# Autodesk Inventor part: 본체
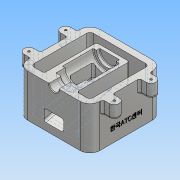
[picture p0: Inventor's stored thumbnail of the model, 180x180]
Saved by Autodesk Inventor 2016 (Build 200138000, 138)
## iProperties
Created: 2018-01
Part Number: 본체
Material: 알루미늄 6061
Document SubType Name: Modeling
Designer: Administrator
Mass: 994.396 g
Surface Area: 835.289 cm^2
Volume: 368.295 cm^3
Density: 2.7 g/cm^3
Appearance: 알루미늄 - 평지
Author: Administrator
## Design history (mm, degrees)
sketch "스케치1"
  geometry: L1 (-55, -55)-(55, -55); L2 (55, -55)-(55, 55); L3 (55, 55)-(-55, 55); L4 (-55, 55)-(-55, -55); L5 (-55, -55)-(55, 55); L6 (55, -55)-(-55, 55); 1 further point
  constraints: 12 end point, 2 midpoint, 2 parallel, 1 horizontal, 1 perpendicular
  dimensions: "d0" = 110 distance of L3.end L2.end; "d1" = 110 distance of L2.end L1.end
extrude "돌출1" new body sketch "스케치1" distance "d2" = 65; taper "d3" = 0 deg
sketch "스케치2"
  geometry: L1 (-55, -55)-(55, -55) reference; L2 (55, -55)-(55, 55) reference; L3 (55, 55)-(-55, 55) reference; L4 (-55, 55)-(-55, -55) reference; L5 (25, -55)-(25, 35); L6 (25, 35)-(-25, 35); L7 (-25, 35)-(-25, -55); L8 (-25, -55)-(-55, -55); L9 (-55, 55)-(55, 55); L10 (55, -55)-(55, 55); L11 (55, -55)-(25, -55); L12 (-55, -55)-(-55, 55); L13 (0, 55)-(0, -55); L14 (0, 45)-(-45, 45); L15 (-45, 45)-(-45, -45); L16 (-45, -45)-(-25, -45); L17 (25, -45)-(45, -45); L18 (45, -45)-(45, 45); L19 (45, 45)-(0, 45); 1 further point
  constraints: 30 end point, 6 perpendicular, 6 point on line, 2 collinear, 2 vertical, 1 horizontal, 1 midpoint, 1 parallel, 1 vertical alignment, 1 other
  dimensions: "d4" = 20 distance between parallel lines of L3 L6; "d5" = 50 distance between parallel lines of L5 L7; "d6" = 10 distance between parallel lines of L16 L8; "d7" = 10 distance between parallel lines of L15 L4; "d8" = 10 distance between parallel lines of L3 L14; "d9" = 10 distance between parallel lines of L2 L18
extrude "돌출2" cut sketch "스케치2" stored distance "d10" = 65; taper "d11" = 0 deg
sketch "스케치3"
  geometry: L1 (35, 65)-(35, 0) reference; L2 (-45, 0)-(35, 0) reference; L3 (35, 30)-(-45, 8.564); L4 (-45, 65)-(-45, 0) reference; 1 further point
  constraints: 2 end point, 2 point on line
  dimensions: "d12" = 30 distance from line of L2 L3.start; "d13" = 105 deg angle of L3 L4
extrude "돌출3" cut sketch "스케치3" stored distance "d14" = 65; taper "d15" = 0 deg
sketch "스케치4"
  geometry: L1 (-25, 35)-(-25, -45) reference; L2 (-55, -55)-(55, -55) reference; L3 (55, 55)-(-55, 55) reference; L4 (0, 55)-(0, -55); L5 (-7.5, -55)-(-7.5, -36); L6 (-7.5, -36)-(-16, -36); L7 (-16, -36)-(-16, -22); L8 (-16, -22)-(-20, -22); L9 (-20, -22)-(-20, 25); L10 (-20, 25)-(-15, 25); L11 (-15, 25)-(-15, 30); L12 (-15, 30)-(0, 30); 1 further point
  constraints: 18 end point, 7 perpendicular, 2 midpoint, 2 point on line, 1 vertical
  dimensions: "d16" = 30 diameter of L11 L4; "d17" = 32 diameter of L7 L4; "d18" = 40 diameter of L9 L4; "d19" = 15 diameter of L5 L4; "d20" = 19 distance of L5.start L5.end; "d21" = 14 distance of L6.end L7.end; "d22" = 47 distance of L8.end L9.end; "d23" = 5 distance of L10.end L11.end
revolve "회전1" sketch "스케치4" stored, may be unused: angle "d24" = 90 deg
node "작업 평면1"
sketch "스케치10"
  geometry: L1 (55, -55)-(55, 55) reference; L2 (-55, 55)-(-55, -55) reference; L3 (-55, -55)-(-7.5, -55) reference; L4 (-55, -35.5)-(-65, -35.5); L5 (-65, -35.5)-(-65, -20.5); L6 (-65, -20.5)-(-55, -20.5); L7 (-55, -20.5)-(-55, -35.5); L8 (-55, 20.5)-(-65, 20.5); L9 (-65, 20.5)-(-65, 35.5); L10 (-65, 35.5)-(-55, 35.5); L11 (-55, 35.5)-(-55, 20.5); L12 (-55, 0)-(55, 0); A1 r 7.5 centre (-65, -28) between (-65, -20.5) and (-65, -35.5); A2 r 7.5 centre (-65, 28) between (-65, 35.5) and (-65, 20.5); 1 further point
  constraints: 18 end point, 4 midpoint, 4 parallel, 4 point on circle, 2 centre point, 2 horizontal, 2 perpendicular, 2 point on line
  dimensions: "d44" = 10 distance of L5.end L6.end; "d46" = 7.5 radius of A1; "d47" = 27 distance from line of L3 A1.centre; "d48" = 10 distance of L9.end L10.end; "d49" = 7.5 radius of A2; "d50" = 56 distance of A2.centre A1.centre
extrude "돌출6" join sketch "스케치10" distance "d51" = 20; taper "d52" = 0 deg
hole "구멍1" diameter "d55" = 3.242; stored, may be unused: countersink angle "d59" = 90 deg, drill point angle "d61" = 118 deg; dims "d53" = 10, "d54" = 10, "d56" = 9, "d57" = 4, "d58" = 2, "d60" = 11
sketch "스케치11"
  geometry: L1 (0, 0)-(-65, 0) reference; L2 (0, 0)-(0, 110) reference; 2 further points
  constraints: 1 other
  dimensions: "d62" = 20 distance from line of L2 point (-20, 55); "d63" = 55 distance from line of L1 point (-20, 55)
feature "엠보싱1" sketch "스케치11" dims "d0" = 110, "d1" = 110, "d4" = 20, "d5" = 50, "d6" = 10, "d7" = 10, "d8" = 10, "d9" = 10, "d64" = 0.5, "d65" = 0
fillet "모깎기1" dims "d66" = 15
fillet "모깎기2" dims "d67" = 5
fillet "모깎기3" dims "d68" = 3
fillet "모깎기4" dims "d72" = 3
fillet "모깎기5" dims "d73" = 3
fillet "모깎기6" dims "d74" = 3
fillet "모깎기7" dims "d75" = 3
sketch "스케치12"
  geometry: L1 (-55, 11.061)-(20, 31.157); L2 (-42, 12.474)-(32, 32.302) reference; L3 (32.776, 29.404)-(-41.224, 9.576) reference; L4 (-45, 6.262)-(-45, 65) reference; L5 (-17, 39.243)-(-55, 29.061); L6 (-17, 39.243)-(20, 39.243); L7 (20, 39.243)-(20, 31.157); L8 (-55, 29.061)-(-55, 11.061); L9 (-55, 0)-(-55, 65) reference; L10 (-22, 65)-(-22, 49) reference; L11 (40, 0)-(-40, 0) reference; 1 further point
  constraints: 10 end point, 1 collinear, 1 horizontal, 1 parallel, 1 perpendicular
  dimensions: "d76" = 5 distance between parallel lines of L3 L1; "d78" = 18 distance of L1.start L5.end; "d88" = 5 distance from line of L10 L5.start; "d99" = 75 deg angle of L9 L5; "d100" = 37 distance of L5.start L6.end
extrude "돌출7" cut sketch "스케치12" stored distance "d81" = 30; taper "d82" = 0 deg
sketch "스케치13"
  geometry: L1 (15, 20)-(-15, 20); L2 (-15, 20)-(-15, -17); L3 (-15, -17)-(15, -17); L4 (15, -17)-(15, 20); L5 (-16, -22)-(16, -22) reference; 2 further points
  constraints: 8 end point, 2 parallel, 1 horizontal, 1 midpoint, 1 perpendicular, 1 vertical alignment
  dimensions: "d83" = 30 distance of L3.end L2.end; "d84" = 37 distance of L2.end L1.end; "d85" = 5 distance between parallel lines of L5 L3
extrude "돌출8" cut sketch "스케치13" distance "d86" = 35; taper "d87" = 0 deg
fillet "모깎기8" dims "d90" = 1
chamfer "모따기2" distance "d91" = 1; stored, may be unused: second distance "d92" = 2, angle "d93" = 45 deg
fillet "모깎기9" dims "d94" = 3
fillet "모깎기11" dims "d96" = 3
fillet "모깎기12" dims "d97" = 3
fillet "모깎기13" dims "d98" = 3
fillet "모깎기14" dims "d101" = 3
node "솔리드1"
mirror "대칭1"
mirror "대칭2"
mirror "대칭3"
